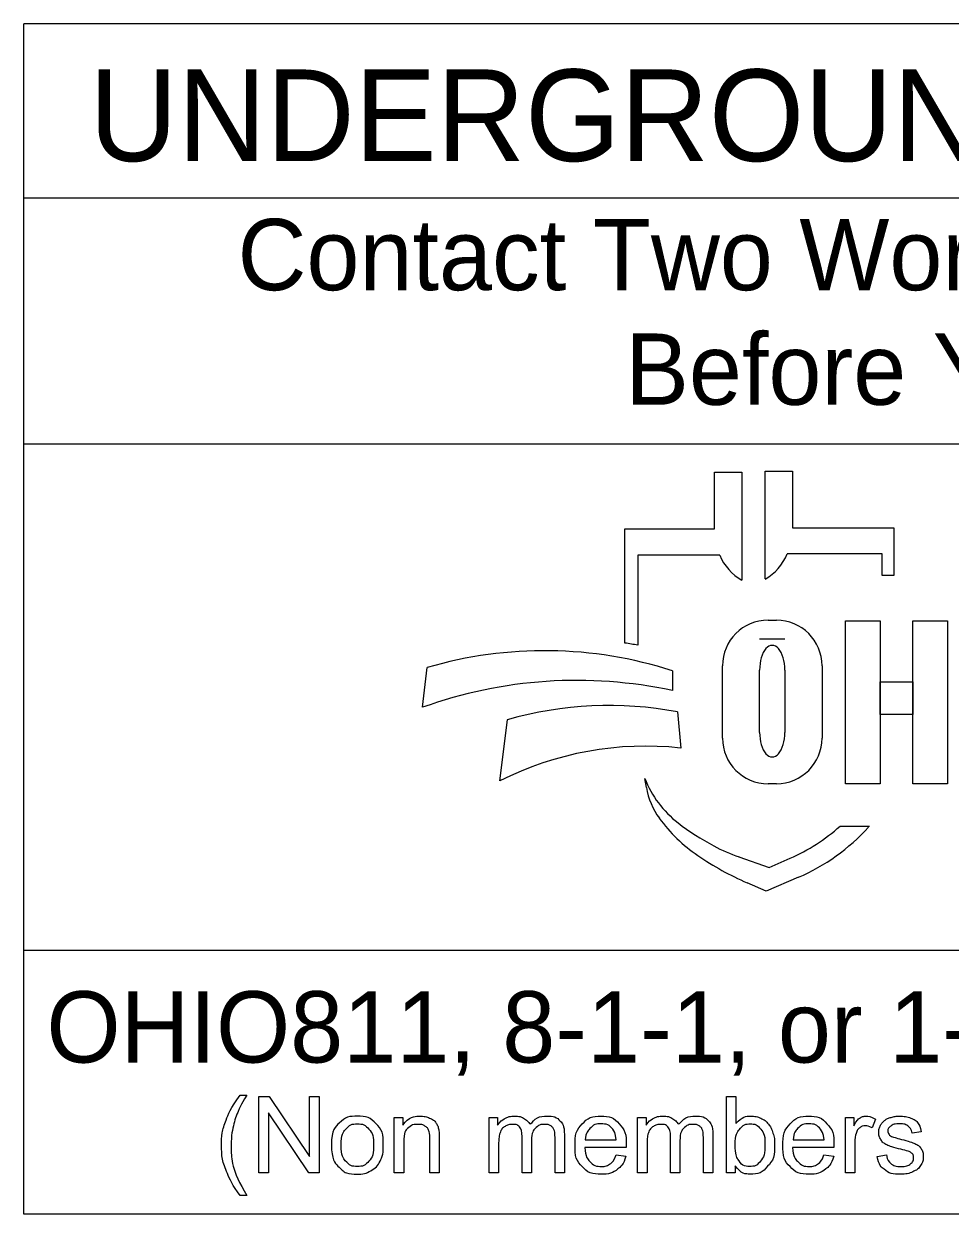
# Model space of a CAD drawing. Extents: x 0 to 44, y -23.8 to 22.
# Drawn here: x 12.402 to 14.221, y -21.643 to -19.305 of the extents above; entities that cross this region are included whole.
import ezdxf

# ---------------------------------------------------------------- set-up
doc = ezdxf.new("R2010")
doc.units = 0
doc.layers.add('SH_Data', color=7, linetype='Continuous')
doc.layers.add('SH_Text', color=7, linetype='Continuous')

msp = doc.modelspace()

# ---------------------------------------------------------------- linework, layer by layer
at = {"layer": 'SH_Data'}
for p, q in [((12.402, -21.6427), (12.402, -19.3052)), ((16.652, -19.3052), (12.402, -19.3052)), ((12.402, -19.6468), (16.652, -19.6468)), ((12.402, -20.1302), (16.652, -20.1302)), ((16.652, -21.1248), (12.402, -21.1248)), ((16.652, -21.6427), (12.402, -21.6427))]:
    msp.add_line(p, q, dxfattribs=at)
at = {"layer": 'SH_Text'}
for p, q in [((13.7581, -20.2972), (13.7581, -20.1857)), ((13.7581, -20.1857), (13.8117, -20.1857)), ((13.8117, -20.1857), (13.8117, -20.3978)), ((13.8574, -20.3954), (13.8574, -20.1834)), ((13.8574, -20.1834), (13.911, -20.1834)), ((13.911, -20.1834), (13.911, -20.2949)), ((13.5821, -20.5211), (13.5821, -20.2972)), ((13.5821, -20.2972), (13.7581, -20.2972)), ((13.911, -20.2949), (14.1103, -20.2949)), ((14.1103, -20.2949), (14.1103, -20.3887)), ((13.6074, -20.3486), (13.6074, -20.5255)), ((13.7685, -20.3486), (13.6074, -20.3486)), ((14.087, -20.3463), (13.9006, -20.3463)), ((14.087, -20.3887), (14.087, -20.3463)), ((14.1103, -20.3887), (14.087, -20.3887)), ((13.8631, -20.4764), (13.8796, -20.4764)), ((13.8963, -20.5134), (13.8465, -20.5134)), ((13.1847, -20.6474), (13.1941, -20.5693)), ((13.7736, -20.7079), (13.7736, -20.5658)), ((13.9691, -20.5658), (13.9691, -20.7079)), ((13.6754, -20.5757), (13.6754, -20.6146)), ((13.8465, -20.6965), (13.8465, -20.5741)), ((13.8963, -20.5741), (13.8963, -20.6965)), ((13.6854, -20.6564), (13.6916, -20.7273)), ((13.3366, -20.7919), (13.3513, -20.6718)), ((13.6243, -20.8048), (13.6212, -20.7869)), ((13.8796, -20.7973), (13.8631, -20.7973)), ((14.0046, -20.8807), (14.062, -20.8807)), ((13.8061, -20.9411), (13.8655, -20.9616)), ((13.8655, -20.9616), (13.9066, -20.9437)), ((13.9228, -20.9811), (13.8595, -21.0086)), ((13.8595, -21.0086), (13.8222, -20.9921))]:
    msp.add_line(p, q, dxfattribs=at)
for points in [[(14.0155, -20.4774), (14.0834, -20.4774), (14.0834, -20.7974), (14.0155, -20.7974)], [(14.1476, -20.4774), (14.2156, -20.4774), (14.2156, -20.7974), (14.1476, -20.7974)], [(14.0834, -20.5973), (14.1476, -20.5973), (14.1476, -20.6613), (14.0834, -20.6613)]]:
    msp.add_lwpolyline(points, close=True, dxfattribs=at)
for points in [[(12.8267, -21.4089), (12.8398, -21.4089)], [(12.8634, -21.5616), (12.8634, -21.4114), (12.8837, -21.4114), (12.9627, -21.5293), (12.9627, -21.4114), (12.9817, -21.4114), (12.9817, -21.5616), (12.9614, -21.5616), (12.8824, -21.4436), (12.8824, -21.5616), (12.8634, -21.5616)], [(13.7989, -21.5616), (13.7818, -21.5616), (13.7818, -21.4114), (13.8002, -21.4114), (13.8002, -21.4649)], [(13.1294, -21.5616), (13.1294, -21.4527), (13.146, -21.4527), (13.146, -21.4682)], [(13.3158, -21.5616), (13.3158, -21.4527), (13.3322, -21.4527), (13.3322, -21.4681)], [(13.6071, -21.5616), (13.6071, -21.4527), (13.6236, -21.4527), (13.6236, -21.4681)], [(14.0149, -21.5616), (14.0149, -21.4527), (14.0315, -21.4527), (14.0315, -21.4692)], [(14.074, -21.4562), (14.0675, -21.4733)], [(14.1639, -21.4809), (14.1458, -21.4833)], [(13.1478, -21.5022), (13.1478, -21.5616), (13.1294, -21.5616)], [(13.2177, -21.4947), (13.2177, -21.5616), (13.1993, -21.5616), (13.1993, -21.4954)], [(13.3989, -21.4984), (13.3989, -21.5616), (13.3804, -21.5616), (13.3804, -21.4909)], [(13.4633, -21.4869), (13.4633, -21.5616), (13.4449, -21.5616), (13.4449, -21.4931)], [(13.5044, -21.4968), (13.5652, -21.4968)], [(13.6902, -21.4984), (13.6902, -21.5616), (13.6718, -21.5616), (13.6718, -21.4909)], [(13.7547, -21.4869), (13.7547, -21.5616), (13.7362, -21.5616), (13.7362, -21.4931)], [(13.9124, -21.4968), (13.9732, -21.4968)], [(14.0333, -21.5046), (14.0333, -21.5616), (14.0149, -21.5616)], [(13.3342, -21.5052), (13.3342, -21.5616), (13.3158, -21.5616)], [(13.5845, -21.5119), (13.5034, -21.5119)], [(13.565, -21.5264), (13.584, -21.5288)], [(13.6256, -21.5052), (13.6256, -21.5616), (13.6071, -21.5616)], [(13.9925, -21.5119), (13.9114, -21.5119)], [(13.9729, -21.5264), (13.992, -21.5288)], [(14.0775, -21.5291), (14.0957, -21.5262)], [(13.7989, -21.5479), (13.7989, -21.5616)], [(12.8398, -21.6057), (12.8267, -21.6057)]]:
    msp.add_lwpolyline(points, dxfattribs=at)
for centre, radius, start, end in [((13.8598, -20.3119), 0.0985, 201.9296, 240.7469), ((13.8093, -20.3095), 0.0985, 299.2531, 338.0704), ((13.8631, -20.5658), 0.0895, 90, 180), ((13.8796, -20.5658), 0.0895, 0, 90), ((13.454, -21.3301), 0.8191, 79.2074, 81.0007), ((13.4242, -21.3553), 0.8191, 72.1402, 106.3144), ((13.4873, -21.4864), 0.8919, 77.8238, 109.8274), ((13.5512, -21.3761), 0.7322, 79.44, 105.8467), ((13.8631, -20.7079), 0.0895, 180, 270), ((13.8796, -20.7079), 0.0895, 270, 0), ((13.6232, -21.3593), 0.6357, 83.8248, 116.8021), ((13.8086, -20.7148), 0.2008, 201.0457, 232.5314), ((13.7656, -20.7807), 0.1433, 189.6817, 216.0884), ((13.8992, -20.6833), 0.3088, 216.0884, 235.7167), ((14.0011, -20.4636), 0.5173, 232.5314, 241.794), ((13.7632, -20.6133), 0.3602, 293.4582, 312.0712), ((13.7632, -20.6133), 0.401, 293.4582, 317.8286), ((13.916, -20.6224), 0.3371, 241.794, 250.9821), ((14.0657, -20.439), 0.6044, 235.7167, 246.2325)]:
    msp.add_arc(centre, radius, start, end, dxfattribs=at)
for centre, start_param, end_param in [((13.8714, -20.5741), 4.712389, 7.853982), ((13.8714, -20.6965), 1.570796, 4.712389)]:
    msp.add_ellipse(centre, major_axis=(0, 0.0484), ratio=0.514403, start_param=start_param, end_param=end_param, dxfattribs=at)
for points in [[(12.8267, -21.6057), (12.8114, -21.5865), (12.8008, -21.5607), (12.7903, -21.5349), (12.7903, -21.5072), (12.7903, -21.4828), (12.7982, -21.4605), (12.8074, -21.4346), (12.8267, -21.4089)], [(12.8398, -21.4089), (12.8274, -21.4302), (12.8235, -21.4393), (12.8172, -21.4534), (12.8137, -21.4688), (12.8093, -21.488), (12.8093, -21.5073), (12.8093, -21.5566), (12.8398, -21.6057)], [(13.0059, -21.5071), (13.0059, -21.4769), (13.0227, -21.4624), (13.0367, -21.4503), (13.0569, -21.4503), (13.0793, -21.4503), (13.0935, -21.465), (13.1077, -21.4797), (13.1077, -21.5056), (13.1077, -21.5266), (13.1014, -21.5386), (13.0951, -21.5507), (13.0831, -21.5573), (13.0711, -21.564), (13.0569, -21.564), (13.034, -21.564), (13.0199, -21.5493), (13.0059, -21.5347), (13.0059, -21.5071)], [(13.146, -21.4682), (13.1579, -21.4503), (13.1805, -21.4503), (13.1904, -21.4503), (13.1986, -21.4539), (13.2069, -21.4574), (13.211, -21.4631), (13.215, -21.4689), (13.2167, -21.4768), (13.2177, -21.4819), (13.2177, -21.4947)], [(13.3322, -21.4681), (13.3374, -21.4601), (13.3459, -21.4552), (13.3544, -21.4503), (13.3652, -21.4503), (13.3773, -21.4503), (13.3851, -21.4554), (13.3928, -21.4604), (13.396, -21.4694), (13.4089, -21.4503), (13.4296, -21.4503), (13.4458, -21.4503), (13.4546, -21.4593), (13.4633, -21.4683), (13.4633, -21.4869)], [(13.584, -21.5288), (13.5795, -21.5455), (13.5673, -21.5547), (13.5551, -21.564), (13.5362, -21.564), (13.5123, -21.564), (13.4983, -21.5493), (13.4844, -21.5346), (13.4844, -21.5081), (13.4844, -21.4806), (13.4985, -21.4655), (13.5126, -21.4503), (13.5352, -21.4503), (13.557, -21.4503), (13.5708, -21.4652), (13.5846, -21.48), (13.5846, -21.507), (13.5846, -21.5086), (13.5845, -21.5119)], [(13.6236, -21.4681), (13.6287, -21.4601), (13.6372, -21.4552), (13.6458, -21.4503), (13.6566, -21.4503), (13.6687, -21.4503), (13.6764, -21.4554), (13.6842, -21.4604), (13.6874, -21.4694), (13.7003, -21.4503), (13.721, -21.4503), (13.7372, -21.4503), (13.7459, -21.4593), (13.7547, -21.4683), (13.7547, -21.4869)], [(13.8002, -21.4649), (13.8119, -21.4503), (13.83, -21.4503), (13.8401, -21.4503), (13.849, -21.4544), (13.858, -21.4584), (13.8638, -21.4657), (13.8695, -21.4731), (13.8728, -21.4834), (13.8761, -21.4937), (13.8761, -21.5055), (13.8761, -21.5335), (13.8623, -21.5487), (13.8484, -21.564), (13.8291, -21.564), (13.8098, -21.564), (13.7989, -21.5479)], [(13.992, -21.5288), (13.9875, -21.5455), (13.9753, -21.5547), (13.9631, -21.564), (13.9442, -21.564), (13.9203, -21.564), (13.9063, -21.5493), (13.8924, -21.5346), (13.8924, -21.5081), (13.8924, -21.4806), (13.9065, -21.4655), (13.9206, -21.4503), (13.9431, -21.4503), (13.965, -21.4503), (13.9788, -21.4652), (13.9926, -21.48), (13.9926, -21.507), (13.9926, -21.5086), (13.9925, -21.5119)], [(14.0315, -21.4692), (14.0379, -21.4577), (14.0432, -21.454), (14.0486, -21.4503), (14.055, -21.4503), (14.0644, -21.4503), (14.074, -21.4562)], [(14.0957, -21.5262), (14.0973, -21.5372), (14.1043, -21.543), (14.1113, -21.5489), (14.124, -21.5489), (14.1367, -21.5489), (14.1429, -21.5437), (14.149, -21.5385), (14.149, -21.5315), (14.149, -21.5253), (14.1436, -21.5217), (14.1398, -21.5192), (14.1247, -21.5154), (14.1044, -21.5103), (14.0966, -21.5066), (14.0887, -21.5028), (14.0847, -21.4962), (14.0806, -21.4896), (14.0806, -21.4816), (14.0806, -21.4744), (14.0839, -21.4682), (14.0873, -21.462), (14.093, -21.4579), (14.0973, -21.4547), (14.1048, -21.4525), (14.1122, -21.4503), (14.1207, -21.4503), (14.1336, -21.4503), (14.1433, -21.454), (14.1529, -21.4577), (14.1576, -21.464), (14.1622, -21.4703), (14.1639, -21.4809)], [(13.0249, -21.5072), (13.0249, -21.5281), (13.034, -21.5385), (13.0431, -21.5489), (13.0569, -21.5489), (13.0705, -21.5489), (13.0796, -21.5384), (13.0887, -21.528), (13.0887, -21.5065), (13.0887, -21.4864), (13.0796, -21.4759), (13.0704, -21.4655), (13.0569, -21.4655), (13.0431, -21.4655), (13.034, -21.4759), (13.0249, -21.4862), (13.0249, -21.5072)], [(13.1993, -21.4954), (13.1993, -21.4842), (13.1971, -21.4786), (13.195, -21.473), (13.1895, -21.4697), (13.184, -21.4663), (13.1767, -21.4663), (13.1649, -21.4663), (13.1563, -21.4738), (13.1478, -21.4813), (13.1478, -21.5022)], [(13.3804, -21.4909), (13.3804, -21.4786), (13.3759, -21.4725), (13.3714, -21.4663), (13.3612, -21.4663), (13.3534, -21.4663), (13.3468, -21.4704), (13.3401, -21.4745), (13.3372, -21.4824), (13.3342, -21.4903), (13.3342, -21.5052)], [(13.4449, -21.4931), (13.4449, -21.482), (13.4431, -21.4771), (13.4413, -21.4723), (13.4366, -21.4693), (13.4318, -21.4663), (13.4255, -21.4663), (13.414, -21.4663), (13.4064, -21.474), (13.3989, -21.4816), (13.3989, -21.4984)], [(13.5652, -21.4968), (13.5639, -21.483), (13.5582, -21.4761), (13.5494, -21.4654), (13.5353, -21.4654), (13.5226, -21.4654), (13.514, -21.474), (13.5053, -21.4825), (13.5044, -21.4968)], [(13.6718, -21.4909), (13.6718, -21.4786), (13.6673, -21.4725), (13.6628, -21.4663), (13.6525, -21.4663), (13.6447, -21.4663), (13.6381, -21.4704), (13.6315, -21.4745), (13.6285, -21.4824), (13.6256, -21.4903), (13.6256, -21.5052)], [(13.7362, -21.4931), (13.7362, -21.482), (13.7344, -21.4771), (13.7326, -21.4723), (13.7279, -21.4693), (13.7232, -21.4663), (13.7169, -21.4663), (13.7054, -21.4663), (13.6978, -21.474), (13.6902, -21.4816), (13.6902, -21.4984)], [(13.7986, -21.5063), (13.7986, -21.5259), (13.8039, -21.5346), (13.8126, -21.5489), (13.8275, -21.5489), (13.8395, -21.5489), (13.8483, -21.5384), (13.8571, -21.5279), (13.8571, -21.507), (13.8571, -21.4857), (13.8487, -21.4756), (13.8402, -21.4654), (13.8283, -21.4654), (13.8162, -21.4654), (13.8074, -21.4759), (13.7986, -21.4864), (13.7986, -21.5063)], [(13.9732, -21.4968), (13.9719, -21.483), (13.9662, -21.4761), (13.9574, -21.4654), (13.9433, -21.4654), (13.9306, -21.4654), (13.922, -21.474), (13.9133, -21.4825), (13.9124, -21.4968)], [(14.0675, -21.4733), (14.0608, -21.4693), (14.0541, -21.4693), (14.048, -21.4693), (14.0433, -21.473), (14.0385, -21.4766), (14.0364, -21.4831), (14.0333, -21.4929), (14.0333, -21.5046)], [(14.1458, -21.4833), (14.1446, -21.4749), (14.1387, -21.4702), (14.1328, -21.4654), (14.1221, -21.4654), (14.1093, -21.4654), (14.1039, -21.4696), (14.0985, -21.4738), (14.0985, -21.4795), (14.0985, -21.4831), (14.1007, -21.486), (14.103, -21.4889), (14.1078, -21.4909), (14.1106, -21.4919), (14.1241, -21.4956), (14.1437, -21.5008), (14.1515, -21.5041), (14.1592, -21.5075), (14.1636, -21.5138), (14.168, -21.5202), (14.168, -21.5296), (14.168, -21.5388), (14.1627, -21.5469), (14.1573, -21.5551), (14.1471, -21.5595), (14.1369, -21.564), (14.1241, -21.564), (14.1029, -21.564), (14.0917, -21.5552), (14.0806, -21.5464), (14.0775, -21.5291)], [(13.5034, -21.5119), (13.5044, -21.5298), (13.5135, -21.5393), (13.5226, -21.5489), (13.5363, -21.5489), (13.5464, -21.5489), (13.5536, -21.5435), (13.5608, -21.5382), (13.565, -21.5264)], [(13.9114, -21.5119), (13.9124, -21.5298), (13.9215, -21.5393), (13.9306, -21.5489), (13.9442, -21.5489), (13.9544, -21.5489), (13.9616, -21.5435), (13.9687, -21.5382), (13.9729, -21.5264)]]:
    msp.add_open_spline(points, degree=3, dxfattribs=at)

# ---------------------------------------------------------------- texts
for s, height, p in [('UNDERGROUND UTILITIES', 0.18, (12.5302, -19.5748)), ('Contact Two Working Days', 0.14, (12.8217, -19.8283)), ('Before You Dig', 0.14, (13.5829, -20.0533)), ('OHIO811, 8-1-1, or 1-800-362-2764', 0.14, (12.4465, -21.3449))]:
    msp.add_text(s, height=height, dxfattribs=at).set_placement(p)

doc.saveas('drawing.dxf')
